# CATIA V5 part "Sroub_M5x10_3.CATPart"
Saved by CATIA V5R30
Part number: Sroub_M5x10_3
Definition: E 1220_5x10
Nomenclature: E 1220_5x10
Source: Unknown
Description: PART--DESC
Bounding box of the stored display mesh (mm): x -209 to -199, y -94.99 to -85.01, z -223.5 to -213.5
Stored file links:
  E:\Bakalarka\Model\Forma_v7\Sroub_M5x10_3.CATPart
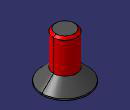
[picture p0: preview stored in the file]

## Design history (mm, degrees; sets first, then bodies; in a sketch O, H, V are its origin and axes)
Body1 "MANIFOLD_SOLID_BREP #4050" (main body)
  Solid1: solid without history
